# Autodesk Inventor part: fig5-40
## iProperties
Created: 2004-05
Part Number: fig5-40
Document SubType Name: Modeling
Designer: CADCIM Technologies
Manufacturer: Standard
Standards Organization: Custom
Density: 1 g/cm^3
Author: CADCIM Technologies
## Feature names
1. Extrusion1
2. Extrusion2
3. Fillet1
4. Hole1
5. Fillet2
6. Mirror1
7. Mirror2
